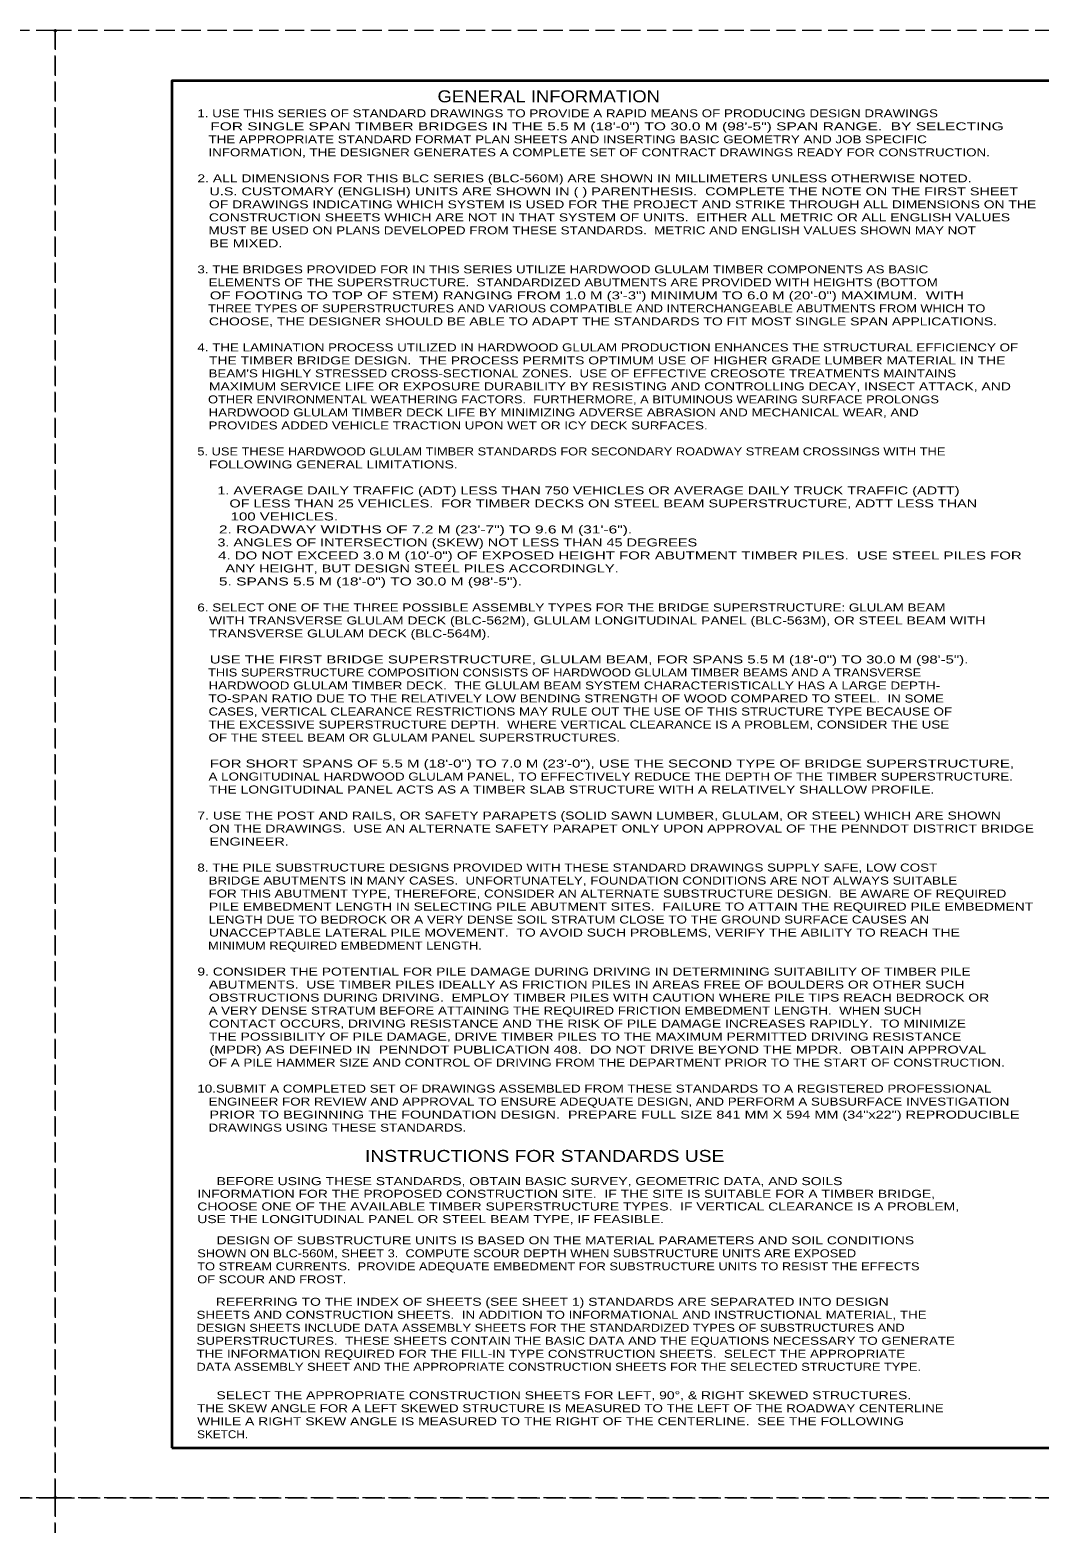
# Model space of a CAD drawing. Extents: x 0 to 68, y -44 to 0.
# Drawn here: x 33.62 to 48.76, y -22.38 to 0.01 of the extents above; entities that cross this region are included whole.
import ezdxf
from ezdxf.enums import TextEntityAlignment as Align

# ---------------------------------------------------------------- set-up
doc = ezdxf.new("R2010")
doc.units = 0
doc.header["$LTSCALE"] = 0.048
doc.header["$PDMODE"] = 32
doc.header["$PDSIZE"] = 0.024
doc.linetypes.add('LONG_DASHED', pattern=[7.5, 6, -1.5])
for name, color, linetype, lineweight in [('1', 7, 'Continuous', 25), ('2', 7, 'Continuous', 35), ('53', 7, 'Continuous', 35), ('63', 7, 'LONG_DASHED', 13)]:
    doc.layers.add(name, color=color, linetype=linetype, lineweight=lineweight)
doc.layers.add('62', color=7, linetype='Continuous')

msp = doc.modelspace()

# ---------------------------------------------------------------- linework, layer by layer
at = {"layer": '1', "lineweight": 35}
msp.add_lwpolyline([(35.75, -21.25), (67.25, -21.25), (67.25, -0.75), (35.75, -0.75)], close=True, dxfattribs=at)
at = {"layer": '62'}
for p in [(34, 0), (34, -22)]:
    msp.add_point(p, dxfattribs=at)
at = {"layer": '63'}
for points in [[(0, -22), (34, -22), (34, 0), (0, 0)], [(34, -22), (68, -22), (68, 0), (34, 0)], [(0, -44), (34, -44), (34, -22), (0, -22)], [(34, -44), (68, -44), (68, -22), (34, -22)]]:
    msp.add_lwpolyline(points, close=True, dxfattribs=at)

# ---------------------------------------------------------------- texts
at = {"layer": '2'}
for s, width, p in [('1. USE THIS SERIES OF STANDARD DRAWINGS TO PROVIDE A RAPID MEANS OF PRODUCING DESIGN DRAWINGS', 1.25, (36.13217, -1.29975)), ('   FOR SINGLE SPAN TIMBER BRIDGES IN THE 5.5 M (18\'-0") TO 30.0 M (98\'-5") SPAN RANGE.  BY SELECTING', 1.45, (36.13217, -1.49475)), ('   THE APPROPRIATE STANDARD FORMAT PLAN SHEETS AND INSERTING BASIC GEOMETRY AND JOB SPECIFIC ', 1.25, (36.13217, -1.68975)), ('   INFORMATION, THE DESIGNER GENERATES A COMPLETE SET OF CONTRACT DRAWINGS READY FOR CONSTRUCTION.', 1.25, (36.13217, -1.88475)), ('2. ALL DIMENSIONS FOR THIS BLC SERIES (BLC-560M) ARE SHOWN IN MILLIMETERS UNLESS OTHERWISE NOTED.', 1.3, (36.13217, -2.27475)), ('   U.S. CUSTOMARY (ENGLISH) UNITS ARE SHOWN IN ( ) PARENTHESIS.  COMPLETE THE NOTE ON THE FIRST SHEET', 1.35, (36.13217, -2.46975)), ('   OF DRAWINGS INDICATING WHICH SYSTEM IS USED FOR THE PROJECT AND STRIKE THROUGH ALL DIMENSIONS ON THE', 1.3, (36.13217, -2.66475)), ('   CONSTRUCTION SHEETS WHICH ARE NOT IN THAT SYSTEM OF UNITS.  EITHER ALL METRIC OR ALL ENGLISH VALUES', 1.3, (36.13217, -2.85975)), ('   MUST BE USED ON PLANS DEVELOPED FROM THESE STANDARDS.  METRIC AND ENGLISH VALUES SHOWN MAY NOT', 1.25, (36.13217, -3.05475)), ('   BE MIXED.', 1.35, (36.13217, -3.24975)), ('3. THE BRIDGES PROVIDED FOR IN THIS SERIES UTILIZE HARDWOOD GLULAM TIMBER COMPONENTS AS BASIC', 1.25, (36.13217, -3.63975)), ('   ELEMENTS OF THE SUPERSTRUCTURE.  STANDARDIZED ABUTMENTS ARE PROVIDED WITH HEIGHTS (BOTTOM', 1.25, (36.13217, -3.83475)), ('   OF FOOTING TO TOP OF STEM) RANGING FROM 1.0 M (3\'-3") MINIMUM TO 6.0 M (20\'-0") MAXIMUM.  WITH', 1.4, (36.13217, -4.02975)), ('   THREE TYPES OF SUPERSTRUCTURES AND VARIOUS COMPATIBLE AND INTERCHANGEABLE ABUTMENTS FROM WHICH TO', 1.2, (36.13217, -4.22475)), ('   CHOOSE, THE DESIGNER SHOULD BE ABLE TO ADAPT THE STANDARDS TO FIT MOST SINGLE SPAN APPLICATIONS.', 1.3, (36.13217, -4.41975)), ('4. THE LAMINATION PROCESS UTILIZED IN HARDWOOD GLULAM PRODUCTION ENHANCES THE STRUCTURAL EFFICIENCY OF ', 1.25, (36.13217, -4.80975)), ('   THE TIMBER BRIDGE DESIGN.  THE PROCESS PERMITS OPTIMUM USE OF HIGHER GRADE LUMBER MATERIAL IN THE ', 1.3, (36.13217, -5.00475)), ("   BEAM'S HIGHLY STRESSED CROSS-SECTIONAL ZONES.  USE OF EFFECTIVE CREOSOTE TREATMENTS MAINTAINS ", 1.25, (36.13217, -5.19975)), ('   MAXIMUM SERVICE LIFE OR EXPOSURE DURABILITY BY RESISTING AND CONTROLLING DECAY, INSECT ATTACK, AND ', 1.3, (36.13217, -5.39475)), ('   OTHER ENVIRONMENTAL WEATHERING FACTORS.  FURTHERMORE, A BITUMINOUS WEARING SURFACE PROLONGS ', 1.2, (36.13217, -5.58975)), ('   HARDWOOD GLULAM TIMBER DECK LIFE BY MINIMIZING ADVERSE ABRASION AND MECHANICAL WEAR, AND ', 1.25, (36.13217, -5.78475)), ('   PROVIDES ADDED VEHICLE TRACTION UPON WET OR ICY DECK SURFACES.', 1.25, (36.13217, -5.97975)), ('5. USE THESE HARDWOOD GLULAM TIMBER STANDARDS FOR SECONDARY ROADWAY STREAM CROSSINGS WITH THE', 1.2, (36.13217, -6.36975)), ('   FOLLOWING GENERAL LIMITATIONS.', 1.3, (36.13217, -6.56475)), ('     1. AVERAGE DAILY TRAFFIC (ADT) LESS THAN 750 VEHICLES OR AVERAGE DAILY TRUCK TRAFFIC (ADTT)', 1.35, (36.13217, -6.95475)), ('        OF LESS THAN 25 VEHICLES.  FOR TIMBER DECKS ON STEEL BEAM SUPERSTRUCTURE, ADTT LESS THAN', 1.35, (36.13217, -7.14975)), ('        100 VEHICLES.', 1.4, (36.13217, -7.34475)), ('     3. ANGLES OF INTERSECTION (SKEW) NOT LESS THAN 45 DEGREES', 1.35, (36.13217, -7.73475)), ('     2. ROADWAY WIDTHS OF 7.2 M (23\'-7") TO 9.6 M (31\'-6").', 1.45, (36.13217, -7.53975)), ('     4. DO NOT EXCEED 3.0 M (10\'-0") OF EXPOSED HEIGHT FOR ABUTMENT TIMBER PILES.  USE STEEL PILES FOR', 1.4, (36.13217, -7.92975)), ('       ANY HEIGHT, BUT DESIGN STEEL PILES ACCORDINGLY.', 1.35, (36.13217, -8.12475)), ('     5. SPANS 5.5 M (18\'-0") TO 30.0 M (98\'-5").', 1.45, (36.13217, -8.31975)), ('6. SELECT ONE OF THE THREE POSSIBLE ASSEMBLY TYPES FOR THE BRIDGE SUPERSTRUCTURE: GLULAM BEAM', 1.25, (36.13217, -8.70975)), ('   WITH TRANSVERSE GLULAM DECK (BLC-562M), GLULAM LONGITUDINAL PANEL (BLC-563M), OR STEEL BEAM WITH ', 1.3, (36.13217, -8.90475)), ('   TRANSVERSE GLULAM DECK (BLC-564M).', 1.3, (36.13217, -9.09975)), ('   USE THE FIRST BRIDGE SUPERSTRUCTURE, GLULAM BEAM, FOR SPANS 5.5 M (18\'-0") TO 30.0 M (98\'-5").', 1.4, (36.13217, -9.48975)), ('   THIS SUPERSTRUCTURE COMPOSITION CONSISTS OF HARDWOOD GLULAM TIMBER BEAMS AND A TRANSVERSE', 1.2, (36.13217, -9.68475)), ('   HARDWOOD GLULAM TIMBER DECK.  THE GLULAM BEAM SYSTEM CHARACTERISTICALLY HAS A LARGE DEPTH-', 1.25, (36.13217, -9.87975)), ('   TO-SPAN RATIO DUE TO THE RELATIVELY LOW BENDING STRENGTH OF WOOD COMPARED TO STEEL.  IN SOME', 1.25, (36.13217, -10.07475)), ('   CASES, VERTICAL CLEARANCE RESTRICTIONS MAY RULE OUT THE USE OF THIS STRUCTURE TYPE BECAUSE OF', 1.25, (36.13217, -10.26975)), ('   THE EXCESSIVE SUPERSTRUCTURE DEPTH.  WHERE VERTICAL CLEARANCE IS A PROBLEM, CONSIDER THE USE', 1.25, (36.13217, -10.46475)), ('   OF THE STEEL BEAM OR GLULAM PANEL SUPERSTRUCTURES.', 1.25, (36.13217, -10.65975)), ('   FOR SHORT SPANS OF 5.5 M (18\'-0") TO 7.0 M (23\'-0"), USE THE SECOND TYPE OF BRIDGE SUPERSTRUCTURE,', 1.4, (36.13217, -11.04975)), ('   A LONGITUDINAL HARDWOOD GLULAM PANEL, TO EFFECTIVELY REDUCE THE DEPTH OF THE TIMBER SUPERSTRUCTURE.', 1.25, (36.13217, -11.24475)), ('   THE LONGITUDINAL PANEL ACTS AS A TIMBER SLAB STRUCTURE WITH A RELATIVELY SHALLOW PROFILE.', 1.3, (36.13217, -11.43975)), ('7. USE THE POST AND RAILS, OR SAFETY PARAPETS (SOLID SAWN LUMBER, GLULAM, OR STEEL) WHICH ARE SHOWN ', 1.3, (36.13217, -11.82975)), ('   ON THE DRAWINGS.  USE AN ALTERNATE SAFETY PARAPET ONLY UPON APPROVAL OF THE PENNDOT DISTRICT BRIDGE ', 1.3, (36.13217, -12.02475)), ('   ENGINEER.', 1.35, (36.13217, -12.21975)), ('8. THE PILE SUBSTRUCTURE DESIGNS PROVIDED WITH THESE STANDARD DRAWINGS SUPPLY SAFE, LOW COST', 1.25, (36.13217, -12.60975)), ('   BRIDGE ABUTMENTS IN MANY CASES.  UNFORTUNATELY, FOUNDATION CONDITIONS ARE NOT ALWAYS SUITABLE', 1.25, (36.13217, -12.80475)), ('   FOR THIS ABUTMENT TYPE, THEREFORE, CONSIDER AN ALTERNATE SUBSTRUCTURE DESIGN.  BE AWARE OF REQUIRED ', 1.25, (36.13217, -12.99975)), ('   PILE EMBEDMENT LENGTH IN SELECTING PILE ABUTMENT SITES.  FAILURE TO ATTAIN THE REQUIRED PILE EMBEDMENT', 1.3, (36.13217, -13.19475)), ('   LENGTH DUE TO BEDROCK OR A VERY DENSE SOIL STRATUM CLOSE TO THE GROUND SURFACE CAUSES AN ', 1.25, (36.13217, -13.38975)), ('   MINIMUM REQUIRED EMBEDMENT LENGTH.', 1.2, (36.13217, -13.77975)), ('   UNACCEPTABLE LATERAL PILE MOVEMENT.  TO AVOID SUCH PROBLEMS, VERIFY THE ABILITY TO REACH THE', 1.3, (36.13217, -13.58475)), ('9. CONSIDER THE POTENTIAL FOR PILE DAMAGE DURING DRIVING IN DETERMINING SUITABILITY OF TIMBER PILE ', 1.3, (36.13217, -14.16975)), ('   ABUTMENTS.  USE TIMBER PILES IDEALLY AS FRICTION PILES IN AREAS FREE OF BOULDERS OR OTHER SUCH', 1.3, (36.13217, -14.36475)), ('   OBSTRUCTIONS DURING DRIVING.  EMPLOY TIMBER PILES WITH CAUTION WHERE PILE TIPS REACH BEDROCK OR', 1.3, (36.13217, -14.55975)), ('   A VERY DENSE STRATUM BEFORE ATTAINING THE REQUIRED FRICTION EMBEDMENT LENGTH.  WHEN SUCH  ', 1.25, (36.13217, -14.75475)), ('   CONTACT OCCURS, DRIVING RESISTANCE AND THE RISK OF PILE DAMAGE INCREASES RAPIDLY.  TO MINIMIZE', 1.3, (36.13217, -14.94975)), ('   THE POSSIBILITY OF PILE DAMAGE, DRIVE TIMBER PILES TO THE MAXIMUM PERMITTED DRIVING RESISTANCE', 1.3, (36.13217, -15.14475)), ('   (MPDR) AS DEFINED IN  PENNDOT PUBLICATION 408.  DO NOT DRIVE BEYOND THE MPDR.  OBTAIN APPROVAL', 1.35, (36.13217, -15.33975)), ('   OF A PILE HAMMER SIZE AND CONTROL OF DRIVING FROM THE DEPARTMENT PRIOR TO THE START OF CONSTRUCTION.', 1.25, (36.13217, -15.53475)), ('10.SUBMIT A COMPLETED SET OF DRAWINGS ASSEMBLED FROM THESE STANDARDS TO A REGISTERED PROFESSIONAL ', 1.25, (36.13217, -15.92475)), ('   ENGINEER FOR REVIEW AND APPROVAL TO ENSURE ADEQUATE DESIGN, AND PERFORM A SUBSURFACE INVESTIGATION', 1.25, (36.13217, -16.11975)), ('   PRIOR TO BEGINNING THE FOUNDATION DESIGN.  PREPARE FULL SIZE 841 MM X 594 MM (34"x22") REPRODUCIBLE ', 1.35, (36.13217, -16.31475)), ('   DRAWINGS USING THESE STANDARDS.', 1.25, (36.13217, -16.50975)), ('     BEFORE USING THESE STANDARDS, OBTAIN BASIC SURVEY, GEOMETRIC DATA, AND SOILS', 1.3, (36.13175, -17.31242)), ('INFORMATION FOR THE PROPOSED CONSTRUCTION SITE.  IF THE SITE IS SUITABLE FOR A TIMBER BRIDGE, ', 1.3, (36.13175, -17.50242)), ('CHOOSE ONE OF THE AVAILABLE TIMBER SUPERSTRUCTURE TYPES.  IF VERTICAL CLEARANCE IS A PROBLEM, ', 1.3, (36.13175, -17.69242)), ('USE THE LONGITUDINAL PANEL OR STEEL BEAM TYPE, IF FEASIBLE. ', 1.3, (36.13175, -17.88242)), ('     DESIGN OF SUBSTRUCTURE UNITS IS BASED ON THE MATERIAL PARAMETERS AND SOIL CONDITIONS', 1.3, (36.13017, -18.2)), ('SHOWN ON BLC-560M, SHEET 3.  COMPUTE SCOUR DEPTH WHEN SUBSTRUCTURE UNITS ARE EXPOSED', 1.2, (36.13017, -18.395)), ('TO STREAM CURRENTS.  PROVIDE ADEQUATE EMBEDMENT FOR SUBSTRUCTURE UNITS TO RESIST THE EFFECTS', 1.2, (36.13017, -18.59)), ('OF SCOUR AND FROST.', 1.2, (36.13017, -18.785)), ('     REFERRING TO THE INDEX OF SHEETS (SEE SHEET 1) STANDARDS ARE SEPARATED INTO DESIGN', 1.3, (36.11942, -19.12167)), ('SHEETS AND CONSTRUCTION SHEETS.  IN ADDITION TO INFORMATIONAL AND INSTRUCTIONAL MATERIAL, THE', 1.25, (36.11942, -19.31667)), ('DESIGN SHEETS INCLUDE DATA ASSEMBLY SHEETS FOR THE STANDARDIZED TYPES OF SUBSTRUCTURES AND', 1.2, (36.11942, -19.51167)), ('SUPERSTRUCTURES.  THESE SHEETS CONTAIN THE BASIC DATA AND THE EQUATIONS NECESSARY TO GENERATE', 1.25, (36.11942, -19.70667)), ('THE INFORMATION REQUIRED FOR THE FILL-IN TYPE CONSTRUCTION SHEETS.  SELECT THE APPROPRIATE', 1.25, (36.11942, -19.90167)), ('DATA ASSEMBLY SHEET AND THE APPROPRIATE CONSTRUCTION SHEETS FOR THE SELECTED STRUCTURE TYPE.', 1.2, (36.11942, -20.09667)), ('THE SKEW ANGLE FOR A LEFT SKEWED STRUCTURE IS MEASURED TO THE LEFT OF THE ROADWAY CENTERLINE', 1.25, (36.12908, -20.71833)), ('     SELECT THE APPROPRIATE CONSTRUCTION SHEETS FOR LEFT, 90°, & RIGHT SKEWED STRUCTURES.', 1.3, (36.12908, -20.52333)), ('WHILE A RIGHT SKEW ANGLE IS MEASURED TO THE RIGHT OF THE CENTERLINE.  SEE THE FOLLOWING', 1.3, (36.12908, -20.91333)), ('SKETCH.', 1.1, (36.12908, -21.10833))]:
    msp.add_text(s, height=0.12, dxfattribs=dict(at, width=width)).set_placement(p)
at = {"layer": '53'}
for s, width, p in [('GENERAL INFORMATION', 1.15, (41.40413, -1.07475)), ('INSTRUCTIONS FOR STANDARDS USE', 1.2, (41.34317, -16.96483))]:
    msp.add_text(s, height=0.18, dxfattribs=dict(at, width=width)).set_placement(p, align=Align.CENTER)

doc.saveas('drawing.dxf')
